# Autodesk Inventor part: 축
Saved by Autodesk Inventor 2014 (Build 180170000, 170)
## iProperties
Created: 2026-07
Part Number: 축
Material: 일반
Document SubType Name: Modeling
Designer: dg
Density: 1 g/cm^3
Appearance: 기본값
Author: dg
Author: jhkim
Creation Date: 2026-07-02
Sending System: Autodesk Inventor 2027
Preprocessor: ST-DEVELOPER v20.1
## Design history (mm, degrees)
node "축1"
node "솔리드1"
node "기준1"
